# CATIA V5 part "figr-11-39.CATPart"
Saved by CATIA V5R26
Part number: Part1
Bounding box of the stored display mesh (mm): x -177 to 59, y -180 to 60, z 0 to 80
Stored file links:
  D:\_Deepak\CATIA\CATIA V5-6R2016_Deepak\Resources\Part files\Partfiles\c11_catia_v5_6r2016_prt\figr-11-39.CATPart
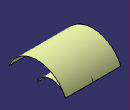
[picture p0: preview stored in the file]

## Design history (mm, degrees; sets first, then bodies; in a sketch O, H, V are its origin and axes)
Set1
  Extrude1: Element1 Sketch1, Lim1 59, Lim2 59, Direction yz-plane
  Scaling1: ToTransfor Extrude1, Reference vertex [face of Extrude1], Ratio 2
Body1 (main body)
  Sketch1 on yz-plane, origin (0, 0, 0), H (0, 1, 0), V (0, 0, 1)
    arc A1 centre (0, -25) radius 65 from (-60, 0) to (60, 0) cw
    point P2 (-60, 0)
    point P3 (60, 0)
    coincidence: P2 H, P3 H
